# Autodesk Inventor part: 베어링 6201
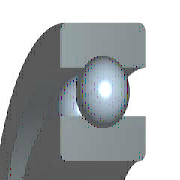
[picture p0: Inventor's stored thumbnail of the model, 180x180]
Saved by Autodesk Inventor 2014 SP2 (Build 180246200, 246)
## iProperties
Created: 2015-12
Part Number: 베어링 6201
Material: 강철, 연강
Description: 깊은 그루브 볼 베어링
Document SubType Name: Modeling
Standard: KS B 2023
Designer: mdu
Standards Organization: KS
Language: ko-KR
Size Designation: 6201 - 12 x 32 x 10
Categories: <MemberInstance><Categories><Category DisplayName="샤프트 부품" InternalName="7f7aeb1f-a693-4053-b835-cee3144e0d98" Mnemonic="SHFT"><Category DisplayName="베어링" Inter
Density: 7.86 g/cm^3
Mass: 36.8026 g
Surface Area: 42.5728 cm^2
Volume: 4.68226 cm^3
Appearance: 진녹색
Company: 한국ATC센터
IsCustomPart: 1
Author: mdu
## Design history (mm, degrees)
sketch "스케치" dims "d0" = 5.2 (= -0.26 x WD + 0.26 x BD)
  geometry: L1 (2.4, 11)-(7.6, 11); L2 (5, 11)-(5, 8.4); L3 (5, 11)-(5, 13.6); L4 (3.068, 9.26)-(0, 9.26); L5 (0, 6)-(10, 6); L6 (3.068, 12.74)-(0, 12.74); L7 (0, 16)-(10, 16); L8 (10, 6)-(10, 9.26); L9 (6.932, 9.26)-(10, 9.26); L10 (6.932, 12.74)-(10, 12.74); L11 (10, 16)-(10, 12.74); L12 (-1.4, 0)-(8.4, 0) reference; L13 (0, -0.3)-(0, 5.3) reference
  constraints: 22 end point, 4 point on line, 2 collinear, 2 perpendicular, 2 symmetric about line, 1 midpoint, 1 parallel, 14 other
  dimensions: "d9" = 12 diameter of L5 L12 (= WD); "d11" = 32 diameter of L7 L12 (= BD); "d12" = 10 distance between parallel lines of L8 L13 (= KB); "d13" = 18.52 diameter of L9 L12 (= 0.326 x BD + 0.674 x WD)
revolve "본체" stored, may be unused: angle "d6" = 90 deg
revolve "볼" stored, may be unused: angle "d7" = 90 deg
pattern_circular "IDS_ARRAYBALL[SIMPL:T]" dims angle "d3" = 360 deg
body "Solid1"
fillet "모깎기1" dims "d1" = 0.6 (= KRS)
other parameters: "WD" = 12 [user parameter; used in 5 equation terms], "BD" = 32 [user parameter; used in 5 equation terms], "KB" = 10 [user parameter; used in 1 equation term], "KRS" = 0.6 [user parameter; used in 1 equation term], "d4" = 0, "d5" = 0, "d8" = 0, "d14" = 0, "d15" = 0, "BBA" = 0 [user parameter], "BC0" = 3100000 [user parameter], "BC" = 6890000 [user parameter], "BR" = 16 (= 0.5 x BD) [user parameter], "WR" = 6 (= 0.5 x WD) [user parameter]
